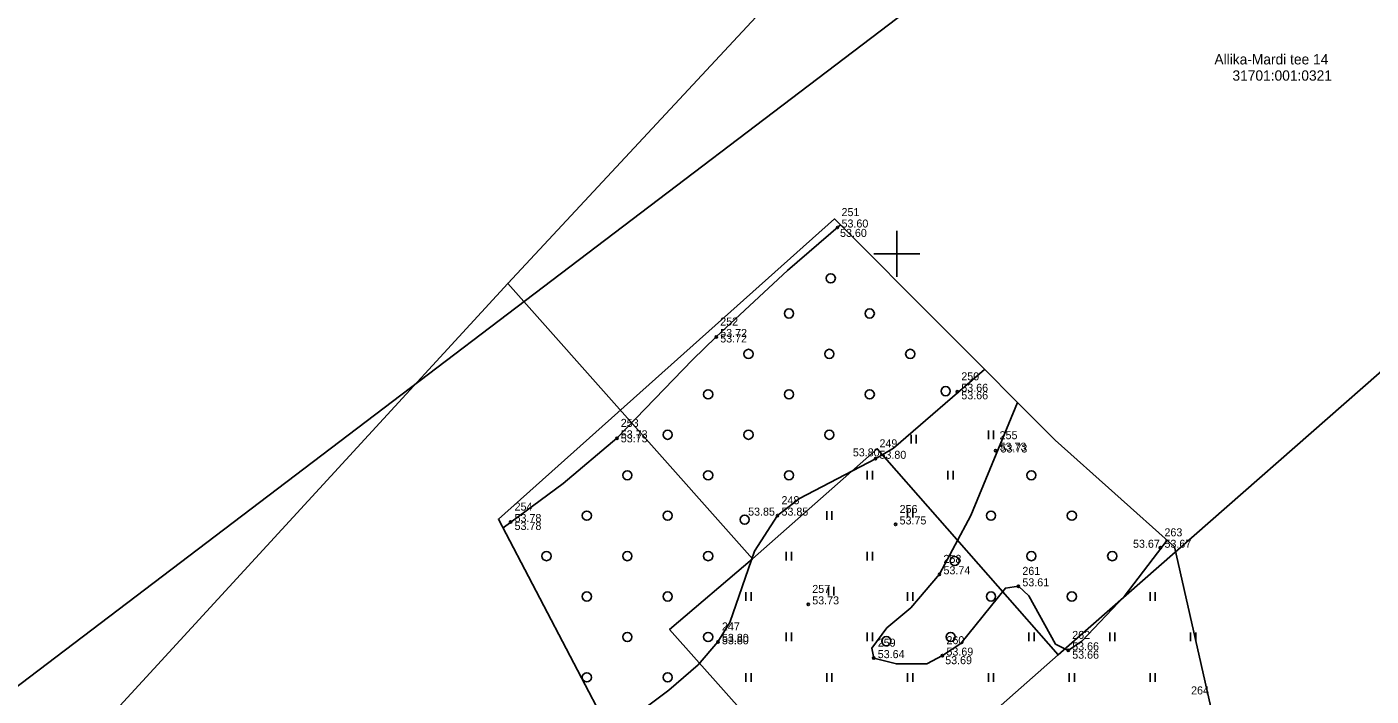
# Model space of a CAD drawing. Extents: x 538599 to 541973, y 6559689 to 6564516.
# Drawn here: x 540273.9 to 540391.5, y 6561511.3 to 6561569.8 of the extents above; entities that cross this region are included whole.
import ezdxf

# ---------------------------------------------------------------- set-up
doc = ezdxf.new("R2010")
doc.units = 0
for name, color, linetype in [('HALJASTUS', 7, 'Continuous'), ('KORGUS-EH2000', 7, 'Continuous'), ('MOOTKORG-EH2000', 7, 'Continuous'), ('MOOTMPUNKT', 7, 'Continuous'), ('MOOTNR', 7, 'Continuous'), ('MOOTPIIR', 7, 'Continuous'), ('PIIR', 7, 'Continuous'), ('VORK', 7, 'Continuous'), ('VORMISTUS', 7, 'Continuous')]:
    doc.layers.add(name, color=color, linetype=linetype)

msp = doc.modelspace()

# ---------------------------------------------------------------- linework, layer by layer
at = {"layer": 'HALJASTUS'}
for p, q in [((540358.01, 6561534.56), (540358.01, 6561533.8)), ((540358.46, 6561534.56), (540358.46, 6561533.8)), ((540351.25, 6561534.17), (540351.25, 6561533.41)), ((540351.7, 6561534.17), (540351.7, 6561533.41)), ((540347.4, 6561531.02), (540347.4, 6561530.26)), ((540347.86, 6561531.02), (540347.86, 6561530.26)), ((540354.47, 6561531.02), (540354.47, 6561530.26)), ((540354.93, 6561531.02), (540354.93, 6561530.26)), ((540343.87, 6561527.49), (540343.87, 6561526.73)), ((540344.32, 6561527.49), (540344.32, 6561526.73)), ((540350.94, 6561527.73), (540350.94, 6561526.96)), ((540351.39, 6561527.73), (540351.39, 6561526.96)), ((540340.33, 6561523.95), (540340.33, 6561523.19)), ((540340.79, 6561523.95), (540340.79, 6561523.19)), ((540347.4, 6561523.95), (540347.4, 6561523.19)), ((540347.86, 6561523.95), (540347.86, 6561523.19)), ((540336.8, 6561520.42), (540336.8, 6561519.66)), ((540337.25, 6561520.42), (540337.25, 6561519.66)), ((540344.02, 6561520.89), (540344.02, 6561520.13)), ((540344.48, 6561520.89), (540344.48, 6561520.13)), ((540350.94, 6561520.42), (540350.94, 6561519.66)), ((540351.39, 6561520.42), (540351.39, 6561519.66)), ((540372.15, 6561520.42), (540372.15, 6561519.66)), ((540372.61, 6561520.42), (540372.61, 6561519.66)), ((540340.33, 6561516.88), (540340.33, 6561516.12)), ((540340.79, 6561516.88), (540340.79, 6561516.12)), ((540347.4, 6561516.88), (540347.4, 6561516.12)), ((540347.86, 6561516.88), (540347.86, 6561516.12)), ((540361.54, 6561516.88), (540361.54, 6561516.12)), ((540362, 6561516.88), (540362, 6561516.12)), ((540368.62, 6561516.88), (540368.62, 6561516.12)), ((540369.07, 6561516.88), (540369.07, 6561516.12)), ((540375.69, 6561516.88), (540375.69, 6561516.12)), ((540376.14, 6561516.88), (540376.14, 6561516.12)), ((540336.8, 6561513.35), (540336.8, 6561512.58)), ((540337.25, 6561513.35), (540337.25, 6561512.58)), ((540343.87, 6561513.35), (540343.87, 6561512.58)), ((540344.32, 6561513.35), (540344.32, 6561512.58)), ((540350.94, 6561513.35), (540350.94, 6561512.58)), ((540351.39, 6561513.35), (540351.39, 6561512.58)), ((540358.01, 6561513.35), (540358.01, 6561512.58)), ((540358.46, 6561513.35), (540358.46, 6561512.58)), ((540365.08, 6561513.35), (540365.08, 6561512.58)), ((540365.53, 6561513.35), (540365.53, 6561512.58)), ((540372.15, 6561513.35), (540372.15, 6561512.58)), ((540372.61, 6561513.35), (540372.61, 6561512.58))]:
    msp.add_line(p, q, dxfattribs=at)
for points in [[(540345.08, 6561552.54), (540340.43, 6561548.53), (540334.2, 6561542.73), (540332.11, 6561540.74), (540325.51, 6561533.87), (540320.82, 6561529.92), (540315.55, 6561526.03)], [(540324.94, 6561508.04), (540330.06, 6561511.84), (540332.61, 6561514.07), (540334.35, 6561516.07), (540335.39, 6561517.77), (540337.56, 6561524), (540339.56, 6561527.11), (540341.47, 6561528.6), (540348.13, 6561532.08), (540349.71, 6561533.01), (540357.68, 6561539.9)], [(540360.55, 6561537.01), (540356.48, 6561527.11), (540353.73, 6561521.98), (540351.22, 6561519.05), (540349.13, 6561517.3), (540347.8, 6561515.51), (540347.98, 6561514.65), (540349.96, 6561514.14), (540352.63, 6561514.14), (540353.99, 6561514.87), (540355.61, 6561515.92), (540359.49, 6561520.77), (540360.63, 6561520.93), (540361.55, 6561520.11), (540363.88, 6561515.88), (540364.99, 6561515.33), (540366.19, 6561516.13), (540369.89, 6561520.05), (540373.65, 6561524.96)]]:
    msp.add_lwpolyline(points, dxfattribs=at)
for centre in [(540344.22, 6561547.86), (540340.56, 6561544.78), (540347.63, 6561544.78), (540337.02, 6561541.25), (540344.09, 6561541.25), (540351.17, 6561541.25), (540333.49, 6561537.71), (540340.56, 6561537.71), (540347.63, 6561537.71), (540354.27, 6561537.99), (540329.95, 6561534.18), (540337.02, 6561534.18), (540344.09, 6561534.18), (540326.42, 6561530.64), (540333.49, 6561530.64), (540340.56, 6561530.64), (540361.77, 6561530.64), (540322.88, 6561527.11), (540329.95, 6561527.11), (540358.24, 6561527.11), (540365.31, 6561527.11), (540336.68, 6561526.76), (540319.35, 6561523.57), (540326.42, 6561523.57), (540333.49, 6561523.57), (540361.77, 6561523.57), (540368.84, 6561523.57), (540355.06, 6561523.14), (540322.88, 6561520.04), (540329.95, 6561520.04), (540358.24, 6561520.04), (540365.31, 6561520.04), (540326.42, 6561516.5), (540333.49, 6561516.5), (540354.7, 6561516.5), (540349.08, 6561516.13), (540322.88, 6561512.97), (540329.95, 6561512.97)]:
    msp.add_circle(centre, 0.4, dxfattribs=at)
at = {"layer": 'KORGUS-EH2000'}
for centre in [(540344.81, 6561552.3), (540334.2, 6561542.73), (540355.29, 6561537.94), (540325.51, 6561533.87), (540348.13, 6561532.08), (540358.64, 6561532.79), (540316.21, 6561526.55), (540339.56, 6561527.11), (540349.89, 6561526.34), (540373.06, 6561524.3), (540360.63, 6561520.93), (540342.25, 6561519.35), (540334.35, 6561516.07), (540347.98, 6561514.65), (540353.99, 6561514.87), (540364.99, 6561515.33)]:
    msp.add_circle(centre, 0.1, dxfattribs=at)
at = {"layer": 'MOOTMPUNKT'}
for centre in [(540344.81, 6561552.3), (540334.2, 6561542.73), (540355.29, 6561537.94), (540325.51, 6561533.87), (540348.13, 6561532.08), (540358.64, 6561532.79), (540316.21, 6561526.55), (540339.56, 6561527.11), (540349.89, 6561526.34), (540373.06, 6561524.3), (540353.73, 6561521.98), (540360.63, 6561520.93), (540342.25, 6561519.35), (540334.35, 6561516.07), (540347.98, 6561514.65), (540353.99, 6561514.87), (540364.99, 6561515.33)]:
    msp.add_circle(centre, 0.1, dxfattribs=at)
at = {"layer": 'MOOTPIIR'}
msp.add_lwpolyline([(540393.81, 6561473.15), (540378.36, 6561490.03), (540367.49, 6561501.89), (540377.47, 6561510.36), (540374.29, 6561524.39), (540363.85, 6561533.7), (540344.56, 6561553.05), (540315.14, 6561526.81), (540325.03, 6561507.91), (540335.62, 6561492.37), (540344.75, 6561491.86), (540356.42, 6561480.19), (540366.31, 6561468.52), (540376.63, 6561456.34), (540384.89, 6561443.84), (540403.97, 6561422.47)], dxfattribs=at)
at = {"layer": 'PIIR'}
msp.add_lwpolyline([(540274.62, 6561658.98), (540308.95, 6561626.96), (540342.1, 6561660.8), (540380.29, 6561616.49), (540315.96, 6561547.42), (540242.15, 6561467.11), (540086.59, 6561298.21), (539860.44, 6561301.54), (539867.53, 6561320.47), (539886.51, 6561388.42), (539892.89, 6561422.22), (539899.82, 6561444.13), (539930.12, 6561502.67), (539948.68, 6561538.36), (539974.66, 6561584.65), (539991.12, 6561609.35), (540012.97, 6561633.62), (540053.54, 6561681.61)], dxfattribs=at)
for points in [[(540315.96, 6561547.42), (540380.29, 6561616.49), (540423.13, 6561566.69), (540364.11, 6561514.94), (540348.28, 6561532.96), (540337.36, 6561523.32)], [(540353.14, 6561505.27), (540364.11, 6561514.94), (540423.13, 6561566.69), (540460.86, 6561522.64), (540391.51, 6561461.86)], [(540242.15, 6561467.11), (540315.96, 6561547.42), (540337.36, 6561523.32), (540330.12, 6561517.14), (540346.17, 6561499.11), (540275.86, 6561428.73)], [(540491.21, 6561183.5), (540566.07, 6561233.36), (540528.84, 6561281.85), (540494.34, 6561324.62), (540458.27, 6561368.69), (540424.68, 6561408.57), (540384.55, 6561455.73), (540346.17, 6561499.11), (540330.12, 6561517.14), (540337.36, 6561523.32), (540348.28, 6561532.96), (540364.11, 6561514.94), (540353.14, 6561505.27), (540391.51, 6561461.86), (540431.74, 6561414.74), (540465.17, 6561374.89), (540501.31, 6561330.86), (540535.92, 6561287.97), (540573.77, 6561238.75), (540640.63, 6561283.66), (540646.74, 6561272.89), (540499, 6561174.36)]]:
    msp.add_lwpolyline(points, close=True, dxfattribs=at)
at = {"layer": 'VORK'}
for p, q in [((540350, 6561552), (540350, 6561548)), ((540348, 6561550), (540352, 6561550))]:
    msp.add_line(p, q, dxfattribs=at)
at = {"layer": 'VORMISTUS'}
msp.add_lwpolyline([(540437.61, 6561637.11), (540710.79, 6561277.18), (540482.18, 6561103.67), (540209, 6561463.6)], close=True, dxfattribs=at)

# ---------------------------------------------------------------- texts
at = {"layer": 'KORGUS-EH2000'}
for s, p in [('53.60', (540345.03, 6561551.48)), ('53.72', (540334.55, 6561542.25)), ('53.66', (540355.64, 6561537.28)), ('53.73', (540325.85, 6561533.52)), ('53.80', (540346.15, 6561532.29)), ('53.73', (540359.07, 6561532.63)), ('53.85', (540336.99, 6561527.11)), ('53.78', (540316.56, 6561525.86)), ('53.75', (540350.24, 6561526.34)), ('53.67', (540370.66, 6561524.3)), ('53.61', (540360.98, 6561520.93)), ('53.73', (540342.6, 6561519.35)), ('53.80', (540334.7, 6561515.86)), ('53.64', (540348.33, 6561514.65)), ('53.69', (540354.23, 6561514.12)), ('53.66', (540365.34, 6561514.6))]:
    msp.add_text(s, height=0.7, dxfattribs=at).set_placement(p)
at = {"layer": 'MOOTKORG-EH2000'}
for s, p in [('53.60', (540345.16, 6561552.3)), ('53.72', (540334.55, 6561542.73)), ('53.66', (540355.64, 6561537.94)), ('53.73', (540325.85, 6561533.87)), ('53.73', (540358.99, 6561532.79)), ('53.80', (540348.48, 6561532.08)), ('53.85', (540339.91, 6561527.11)), ('53.78', (540316.56, 6561526.55)), ('53.75', (540350.24, 6561526.34)), ('53.67', (540373.41, 6561524.3)), ('53.74', (540354.08, 6561521.98)), ('53.61', (540360.98, 6561520.93)), ('53.73', (540342.6, 6561519.35)), ('53.80', (540334.7, 6561516.07)), ('53.66', (540365.34, 6561515.33)), ('53.64', (540348.33, 6561514.65)), ('53.69', (540354.34, 6561514.87))]:
    msp.add_text(s, height=0.7, dxfattribs=at).set_placement(p)
at = {"layer": 'MOOTNR'}
for s, p in [('251', (540345.16, 6561553.3)), ('252', (540334.55, 6561543.73)), ('250', (540355.64, 6561538.94)), ('253', (540325.85, 6561534.87)), ('249', (540348.48, 6561533.08)), ('255', (540358.99, 6561533.79)), ('248', (540339.91, 6561528.11)), ('254', (540316.56, 6561527.55)), ('256', (540350.24, 6561527.34)), ('263', (540373.41, 6561525.3)), ('258', (540354.08, 6561522.98)), ('261', (540360.98, 6561521.93)), ('257', (540342.6, 6561520.35)), ('247', (540334.7, 6561517.07)), ('262', (540365.34, 6561516.33)), ('259', (540348.33, 6561515.65)), ('260', (540354.34, 6561515.87)), ('264', (540375.74, 6561511.48))]:
    msp.add_text(s, height=0.7, dxfattribs=at).set_placement(p)
at = {"layer": 'PIIR'}
for s, p in [('Allika-Mardi tee 14', (540377.78, 6561566.56)), ('31701:001:0321', (540379.36, 6561565.14))]:
    msp.add_text(s, height=0.9, rotation=0, dxfattribs=at).set_placement(p)

doc.saveas('drawing.dxf')
